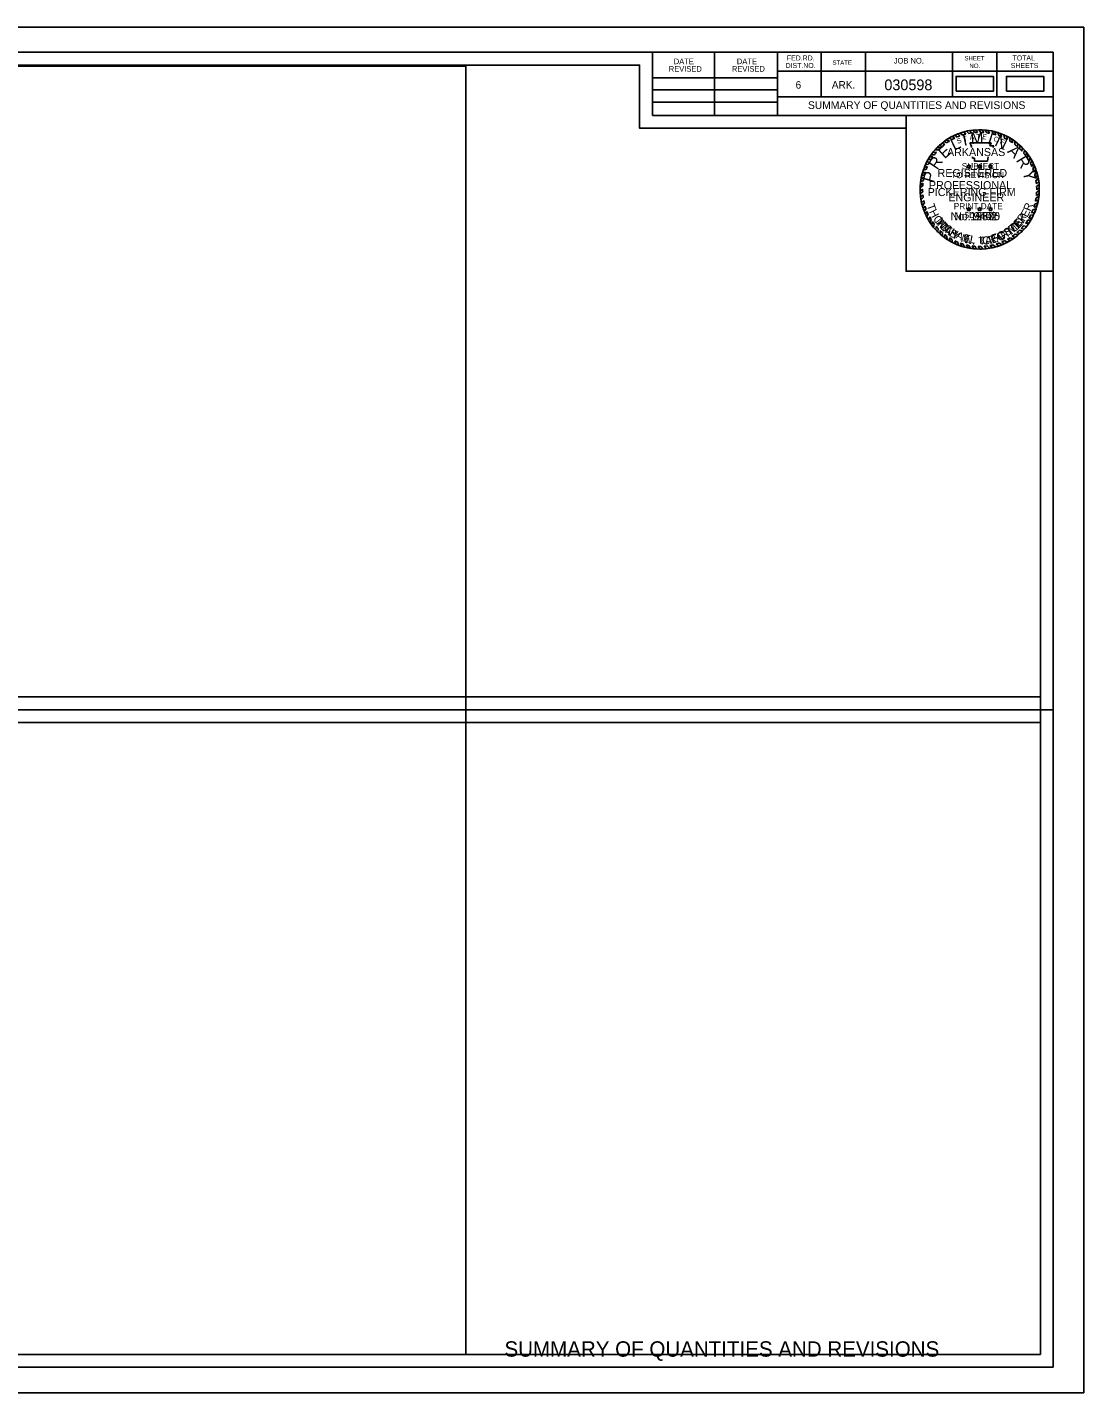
# Model space of a CAD drawing. Extents: x 1369904 to 1372237, y 380119 to 380332.
# Drawn here: x 1372071.9 to 1372236.9, y 380119.1 to 380332.4 of the extents above; entities that cross this region are included whole.
import ezdxf

# ---------------------------------------------------------------- set-up
doc = ezdxf.new("R2010")
doc.units = 0
for name, color, linetype in [('Default', 7, 'Continuous'), ('R_Border', 7, 'Continuous'), ('R_Border Notes', 7, 'Continuous'), ('R_Border Plan-Plan', 7, 'Continuous'), ('R_Border Title', 7, 'Continuous'), ('R_No Plot', 7, 'Continuous'), ('STAMP_PE_CRAFTON', 7, 'Continuous'), ('STAMP_PE_FOSTER', 7, 'Continuous'), ('STAMP_PE_SEAL-INFO', 7, 'Continuous'), ('STAMP_PE_TAEGTMEYER', 7, 'Continuous'), ('STAMP_PE_TXT', 7, 'Continuous'), ('STAMP_PRELIMINARY', 7, 'Continuous')]:
    doc.layers.add(name, color=color, linetype=linetype)

msp = doc.modelspace()

# ---------------------------------------------------------------- linework, layer by layer
at = {"layer": 'Default'}
for points in [[(1371973.99, 380125.04), (1372140.37, 380125.04), (1372140.37, 380326.31), (1371973.99, 380326.31)], [(1372217, 380322.41), (1372222.83, 380322.41), (1372222.83, 380324.72), (1372217, 380324.72)], [(1372224.87, 380322.41), (1372230.7, 380322.41), (1372230.7, 380324.72), (1372224.87, 380324.72)]]:
    msp.add_lwpolyline(points, close=True, dxfattribs=at)
at = {"layer": 'R_Border'}
for p, q in [((1371916, 380328.5), (1372232.18, 380328.5)), ((1372169.54, 380318.62), (1372169.54, 380328.5)), ((1372179.22, 380318.62), (1372179.22, 380328.5)), ((1372189.08, 380328.5), (1372189.08, 380318.62)), ((1372195.92, 380328.5), (1372195.92, 380321.56)), ((1372202.86, 380328.5), (1372202.86, 380321.56)), ((1372216.44, 380328.5), (1372216.44, 380321.56)), ((1372223.38, 380328.5), (1372223.38, 380321.56)), ((1372232.18, 380123.04), (1372232.18, 380328.5)), ((1372232.18, 380325.56), (1372189.08, 380325.56)), ((1372232.18, 380325.58), (1372232.18, 380325.58)), ((1372169.54, 380324.48), (1372189.08, 380324.48)), ((1372169.54, 380322.62), (1372189.08, 380322.62)), ((1372232.18, 380321.56), (1372189.08, 380321.56)), ((1372192.04, 380321.56), (1372232.18, 380321.56)), ((1372169.54, 380320.68), (1372189.08, 380320.68)), ((1372232.18, 380318.62), (1372169.54, 380318.62)), ((1372232.18, 380123.04), (1371916, 380123.04))]:
    msp.add_line(p, q, dxfattribs=at)
at = {"layer": 'R_Border Plan-Plan'}
msp.add_line((1371916, 380225.77), (1372232.18, 380225.77), dxfattribs=at)
at = {"layer": 'R_No Plot'}
for points in [[(1371903.6, 380332.4), (1372236.94, 380332.4), (1372236.94, 380119.06), (1371903.6, 380119.06)], [(1372230.18, 380227.77), (1371918, 380227.77), (1371918, 380326.5), (1372167.54, 380326.5), (1372167.54, 380316.62), (1372185.08, 380316.62), (1372209.18, 380316.62), (1372209.18, 380294.29), (1372230.18, 380294.29)], [(1371918, 380326.5), (1372167.54, 380326.5), (1372167.54, 380316.62), (1372185.08, 380316.62), (1372209.18, 380316.62), (1372209.18, 380294.29), (1372230.18, 380294.29), (1372230.18, 380125.04), (1371918, 380125.04)], [(1372209.18, 380318.62), (1372232.18, 380318.62), (1372232.18, 380294.29), (1372209.18, 380294.29)], [(1371918, 380223.77), (1372230.18, 380223.77), (1372230.18, 380125.04), (1371918, 380125.04)]]:
    msp.add_lwpolyline(points, close=True, dxfattribs=at)
at = {"layer": 'STAMP_PE_SEAL-INFO'}
for p, q in [((1372215.52, 380314.83), (1372215.96, 380314.63)), ((1372215.91, 380315.07), (1372216.34, 380314.85)), ((1372216.36, 380315.33), (1372216.82, 380315.1)), ((1372216.79, 380315.54), (1372217.18, 380315.26)), ((1372217.29, 380315.75), (1372217.59, 380315.43)), ((1372217.64, 380315.88), (1372218.02, 380315.57)), ((1372218.23, 380316.06), (1372218.52, 380315.71)), ((1372218.62, 380316.16), (1372218.98, 380315.82)), ((1372219.1, 380316.26), (1372219.4, 380315.89)), ((1372219.62, 380316.33), (1372219.9, 380315.95)), ((1372220.35, 380315.97), (1372220.04, 380316.37)), ((1372220.85, 380315.98), (1372220.57, 380316.39)), ((1372221.31, 380315.96), (1372221.05, 380316.38)), ((1372221.82, 380315.91), (1372221.52, 380316.35)), ((1372222.24, 380315.84), (1372221.98, 380316.3)), ((1372222.8, 380315.72), (1372222.63, 380316.18)), ((1372223.21, 380315.62), (1372223.05, 380316.09)), ((1372223.66, 380315.47), (1372223.52, 380315.95)), ((1372224.08, 380315.31), (1372223.93, 380315.81)), ((1372224.54, 380315.1), (1372224.43, 380315.6)), ((1372224.98, 380314.87), (1372224.9, 380315.38)), ((1372225.37, 380314.65), (1372225.33, 380315.15)), ((1372225.81, 380314.36), (1372225.77, 380314.88)), ((1372213.38, 380312.86), (1372213.93, 380312.88)), ((1372213.72, 380313.27), (1372214.24, 380313.23)), ((1372214.04, 380313.61), (1372214.59, 380313.57)), ((1372214.38, 380313.94), (1372214.84, 380313.8)), ((1372214.72, 380314.24), (1372215.25, 380314.14)), ((1372215.1, 380314.56), (1372215.56, 380314.36)), ((1372219.16, 380314.36), (1372222.5, 380314.36)), ((1372219.28, 380314.05), (1372219.16, 380314.36)), ((1372219.38, 380313.75), (1372219.28, 380314.05)), ((1372219.39, 380313.64), (1372219.38, 380313.75)), ((1372222.5, 380314.36), (1372222.28, 380313.87)), ((1372222.28, 380313.87), (1372222.91, 380313.87)), ((1372222.91, 380313.87), (1372222.76, 380313.64)), ((1372226.17, 380314.1), (1372226.2, 380314.58)), ((1372226.61, 380313.72), (1372226.63, 380314.25)), ((1372226.92, 380313.43), (1372226.99, 380313.93)), ((1372227.28, 380313.06), (1372227.35, 380313.58)), ((1372227.56, 380312.74), (1372227.69, 380313.21)), ((1372227.88, 380312.32), (1372228.02, 380312.82)), ((1372212.01, 380310.5), (1372212.52, 380310.64)), ((1372212.2, 380310.93), (1372212.7, 380311.03)), ((1372212.39, 380311.32), (1372212.88, 380311.38)), ((1372212.62, 380311.74), (1372213.11, 380311.76)), ((1372212.86, 380312.14), (1372213.38, 380312.18)), ((1372213.1, 380312.49), (1372213.6, 380312.48)), ((1372219.58, 380311.93), (1372219.55, 380312.15)), ((1372219.89, 380311.93), (1372219.58, 380311.93)), ((1372219.89, 380311.5), (1372219.89, 380311.93)), ((1372221.92, 380311.5), (1372219.89, 380311.5)), ((1372221.94, 380311.84), (1372221.92, 380311.5)), ((1372222.02, 380312.15), (1372221.94, 380311.84)), ((1372228.1, 380312.01), (1372228.28, 380312.47)), ((1372228.41, 380311.51), (1372228.59, 380312)), ((1372228.61, 380311.14), (1372228.84, 380311.59)), ((1372228.84, 380310.66), (1372229.07, 380311.15)), ((1372228.98, 380310.32), (1372229.24, 380310.76)), ((1372211.88, 380308.48), (1372211.44, 380308.25)), ((1372211.97, 380308.94), (1372211.5, 380308.69)), ((1372211.6, 380309.18), (1372212.07, 380309.37)), ((1372211.71, 380309.59), (1372212.19, 380309.76)), ((1372211.86, 380310.09), (1372212.35, 380310.23)), ((1372229.18, 380309.77), (1372229.45, 380310.25)), ((1372229.28, 380309.41), (1372229.58, 380309.86)), ((1372229.42, 380308.85), (1372229.73, 380309.3)), ((1372229.49, 380308.47), (1372229.84, 380308.82)), ((1372211.79, 380307.62), (1372211.36, 380307.36)), ((1372211.77, 380307.12), (1372211.36, 380306.79)), ((1372211.78, 380306.72), (1372211.38, 380306.39)), ((1372211.82, 380308.04), (1372211.39, 380307.76)), ((1372229.55, 380307.96), (1372229.92, 380308.3)), ((1372229.55, 380306.11), (1372229.98, 380306.37)), ((1372229.58, 380307.54), (1372229.97, 380307.84)), ((1372229.59, 380306.62), (1372230, 380306.9)), ((1372229.6, 380307.03), (1372230, 380307.35)), ((1372211.81, 380306.22), (1372211.44, 380305.86)), ((1372211.86, 380305.79), (1372211.51, 380305.42)), ((1372211.94, 380305.33), (1372211.6, 380304.96)), ((1372212.03, 380304.91), (1372211.72, 380304.5)), ((1372212.16, 380304.47), (1372211.86, 380304.05)), ((1372229.15, 380304.28), (1372229.64, 380304.48)), ((1372229.3, 380304.77), (1372229.77, 380304.98)), ((1372229.4, 380305.23), (1372229.86, 380305.42)), ((1372229.49, 380305.73), (1372229.94, 380305.95)), ((1372212.3, 380304.04), (1372212.02, 380303.63)), ((1372212.46, 380303.62), (1372212.2, 380303.19)), ((1372212.64, 380303.23), (1372212.41, 380302.77)), ((1372212.87, 380302.77), (1372212.68, 380302.28)), ((1372213.11, 380302.37), (1372212.92, 380301.9)), ((1372213.31, 380302.06), (1372213.2, 380301.51)), ((1372228.2, 380302.27), (1372228.67, 380302.26)), ((1372228.37, 380302.55), (1372228.87, 380302.61)), ((1372228.64, 380303.05), (1372229.13, 380303.12)), ((1372228.8, 380303.39), (1372229.29, 380303.48)), ((1372229.01, 380303.9), (1372229.5, 380304.03)), ((1372213.59, 380301.67), (1372213.49, 380301.14)), ((1372213.89, 380301.29), (1372213.81, 380300.77)), ((1372214.2, 380300.95), (1372214.13, 380300.43)), ((1372214.52, 380300.63), (1372214.49, 380300.1)), ((1372214.86, 380300.32), (1372214.86, 380299.79)), ((1372215.22, 380300.02), (1372215.24, 380299.5)), ((1372226.23, 380300.09), (1372226.7, 380299.95)), ((1372226.5, 380300.32), (1372226.98, 380300.19)), ((1372226.91, 380300.69), (1372227.35, 380300.55)), ((1372227.16, 380300.95), (1372227.64, 380300.86)), ((1372227.55, 380301.38), (1372228.01, 380301.3)), ((1372227.86, 380301.78), (1372228.36, 380301.78)), ((1372215.56, 380299.77), (1372215.6, 380299.25)), ((1372215.99, 380299.49), (1372216.05, 380298.98)), ((1372216.34, 380299.28), (1372216.43, 380298.77)), ((1372216.82, 380299.03), (1372216.98, 380298.51)), ((1372217.19, 380298.87), (1372217.37, 380298.35)), ((1372217.69, 380298.67), (1372217.89, 380298.17)), ((1372218.09, 380298.54), (1372218.32, 380298.05)), ((1372218.6, 380298.4), (1372218.82, 380297.93)), ((1372219, 380298.31), (1372219.25, 380297.86)), ((1372219.5, 380298.23), (1372219.74, 380297.79)), ((1372219.94, 380298.19), (1372220.21, 380297.76)), ((1372220.42, 380298.16), (1372220.72, 380297.74)), ((1372220.88, 380298.16), (1372221.23, 380297.76)), ((1372221.4, 380298.18), (1372221.73, 380297.8)), ((1372221.84, 380298.23), (1372222.21, 380297.87)), ((1372222.28, 380298.3), (1372222.67, 380297.96)), ((1372222.78, 380298.4), (1372223.15, 380298.08)), ((1372223.24, 380298.53), (1372223.65, 380298.23)), ((1372223.73, 380298.69), (1372224.17, 380298.42)), ((1372224.15, 380298.85), (1372224.57, 380298.59)), ((1372224.61, 380299.06), (1372225.09, 380298.85)), ((1372225.01, 380299.28), (1372225.43, 380299.04)), ((1372225.43, 380299.52), (1372225.88, 380299.33)), ((1372225.77, 380299.75), (1372226.21, 380299.56))]:
    msp.add_line(p, q, dxfattribs=at)
for radius, start, end in [(9.32, 123.6199, 126.5906), (9.32, 117.6544, 120.8099), (8.91, 115.6869, 119.1583), (9.32, 111.3124, 114.7026), (8.91, 110.3086, 113.1659), (9.32, 105.2339, 109.0352), (8.91, 104.0352, 107.3615), (9.32, 99.7525, 102.7765), (8.91, 98.258, 101.0329), (9.32, 93.9381, 96.5517), (8.91, 92.1102, 95.0367), (9.32, 87.7298, 90.6707), (8.91, 85.9628, 88.9097), (9.32, 81.9732, 84.8236), (8.91, 79.9264, 82.696), (9.32, 75.3125, 77.9426), (8.91, 73.5575, 76.2314), (9.32, 69.6061, 72.3058), (8.91, 67.6248, 70.504), (9.32, 63.1329, 66.2704), (8.91, 61.1558, 64.3784), (9.32, 56.9003, 60.0942), (9.32, 141.6056, 144.4486), (8.91, 139.301, 142.5873), (9.32, 135.4021, 138.3031), (8.91, 133.1331, 136.2562), (9.32, 129.7326, 132.5376), (8.91, 127.5297, 130.9683), (8.91, 121.9746, 125.11), (8.91, 54.9238, 58.2702), (8.91, 48.3016, 52.0395), (9.32, 50.3492, 53.7159), (8.91, 42.2212, 45.5512), (9.32, 44.3405, 47.3929), (8.91, 36.135, 39.5311), (9.32, 38.1247, 41.2316), (9.32, 152.864, 155.5189), (8.91, 156.3402, 159.2319), (9.32, 147.0072, 149.899), (8.91, 151.0315, 153.573), (8.91, 145.0197, 148.2104), (8.91, 29.9032, 33.6645), (9.32, 31.9614, 35.4294), (8.91, 23.7732, 27.2211), (9.32, 25.9391, 29.0125), (9.32, 19.9538, 23.3141), (9.32, 170.0003, 172.6878), (9.32, 164.3068, 166.894), (9.32, 158.4077, 161.0701), (8.91, 167.9048, 170.9039), (8.91, 162.4331, 165.0013), (8.91, 17.6802, 21.4251), (8.91, 11.5444, 15.2364), (8.91, 5.7599, 9.0606), (9.32, 13.8421, 17.4447), (9.32, 7.5852, 10.8621), (9.32, 175.7409, 178.2066), (9.32, 181.7251, 184.1626), (8.91, 179.6454, 182.2633), (8.91, 173.73, 176.4734), (8.91, 353.8632, 357.1274), (8.91, 359.7329, 3.0639), (9.32, 1.7215, 4.7268), (9.32, 355.7156, 358.9569), (9.32, 187.4204, 190.1927), (9.32, 193.0369, 195.9973), (8.91, 185.4539, 188.234), (8.91, 191.2274, 193.9858), (8.91, 196.9675, 199.8353), (8.91, 341.777, 345.0925), (8.91, 348.0778, 351.3435), (9.32, 343.8925, 347.035), (9.32, 349.8305, 353.0885), (9.32, 198.8967, 201.6281), (9.32, 204.5479, 207.4328), (8.91, 202.7761, 205.4791), (9.32, 210.8636, 213.6571), (8.91, 208.7883, 211.7934), (8.91, 214.1838, 217.2747), (8.91, 323.5851, 327.4407), (9.32, 325.4405, 328.9872), (8.91, 329.5549, 333.2076), (8.91, 335.6038, 339.1858), (9.32, 331.4037, 334.9332), (9.32, 337.3837, 340.9933), (9.32, 216.6115, 219.491), (9.32, 222.48, 225.3801), (8.91, 220.3909, 223.3056), (9.32, 228.3665, 231.348), (8.91, 226.2494, 229.2407), (8.91, 232.229, 234.9336), (8.91, 304.823, 308.5143), (9.32, 306.3721, 310.208), (8.91, 310.7744, 314.3161), (9.32, 312.4518, 315.6633), (8.91, 316.6531, 320.3711), (9.32, 318.2846, 321.8043), (9.32, 234.295, 236.9452), (8.91, 238.2223, 240.8353), (9.32, 240.1977, 242.8613), (8.91, 244.3204, 246.9486), (9.32, 246.576, 249.1558), (8.91, 250.3491, 253.1216), (9.32, 252.5967, 255.3252), (8.91, 256.505, 259.1192), (9.32, 258.4433, 261.1398), (8.91, 262.3783, 265.2012), (9.32, 264.1978, 267.1009), (8.91, 268.3215, 271.277), (9.32, 270.2548, 273.3361), (8.91, 274.6157, 277.4486), (9.32, 276.4239, 279.4357), (8.91, 280.3459, 283.5814), (9.32, 282.3199, 285.3702), (8.91, 286.6423, 289.9783), (9.32, 288.5709, 291.9733), (8.91, 292.8745, 296.1185), (9.32, 294.6481, 298.2166), (8.91, 299.0768, 302.1724), (9.32, 300.621, 303.8703)]:
    msp.add_arc((1372220.68, 380307.07), radius, start, end, dxfattribs=at)
at = {"layer": 'STAMP_PE_TXT'}
for p, q in [((1372218.86, 380310.64), (1372218.66, 380310.78)), ((1372218.66, 380310.78), (1372218.91, 380310.78)), ((1372218.79, 380310.41), (1372218.86, 380310.64)), ((1372218.98, 380310.55), (1372218.79, 380310.41)), ((1372218.91, 380310.78), (1372218.98, 380311.02)), ((1372218.98, 380311.02), (1372219.06, 380310.78)), ((1372219.18, 380310.41), (1372218.98, 380310.55)), ((1372219.06, 380310.78), (1372219.31, 380310.78)), ((1372219.31, 380310.78), (1372219.11, 380310.64)), ((1372219.11, 380310.64), (1372219.18, 380310.41)), ((1372220.56, 380310.64), (1372220.36, 380310.78)), ((1372220.36, 380310.78), (1372220.61, 380310.78)), ((1372220.48, 380310.41), (1372220.56, 380310.64)), ((1372220.68, 380310.55), (1372220.48, 380310.41)), ((1372220.61, 380310.78), (1372220.68, 380311.02)), ((1372220.68, 380311.02), (1372220.76, 380310.78)), ((1372220.88, 380310.41), (1372220.68, 380310.55)), ((1372220.76, 380310.78), (1372221, 380310.78)), ((1372221, 380310.78), (1372220.81, 380310.64)), ((1372220.81, 380310.64), (1372220.88, 380310.41)), ((1372222.26, 380310.64), (1372222.06, 380310.78)), ((1372222.06, 380310.78), (1372222.31, 380310.78)), ((1372222.18, 380310.41), (1372222.26, 380310.64)), ((1372222.38, 380310.55), (1372222.18, 380310.41)), ((1372222.31, 380310.78), (1372222.38, 380311.02)), ((1372222.38, 380311.02), (1372222.46, 380310.78)), ((1372222.58, 380310.41), (1372222.38, 380310.55)), ((1372222.46, 380310.78), (1372222.7, 380310.78)), ((1372222.7, 380310.78), (1372222.5, 380310.64)), ((1372222.5, 380310.64), (1372222.58, 380310.41)), ((1372218.91, 380304.08), (1372218.98, 380304.31)), ((1372218.98, 380304.31), (1372219.06, 380304.08)), ((1372220.61, 380304.08), (1372220.68, 380304.31)), ((1372220.68, 380304.31), (1372220.76, 380304.08)), ((1372222.31, 380304.08), (1372222.38, 380304.31)), ((1372222.38, 380304.31), (1372222.46, 380304.08)), ((1372218.86, 380303.93), (1372218.66, 380304.08)), ((1372218.66, 380304.08), (1372218.91, 380304.08)), ((1372218.79, 380303.7), (1372218.86, 380303.93)), ((1372218.98, 380303.84), (1372218.79, 380303.7)), ((1372219.18, 380303.7), (1372218.98, 380303.84)), ((1372219.06, 380304.08), (1372219.31, 380304.08)), ((1372219.31, 380304.08), (1372219.11, 380303.93)), ((1372219.11, 380303.93), (1372219.18, 380303.7)), ((1372220.56, 380303.93), (1372220.36, 380304.08)), ((1372220.36, 380304.08), (1372220.61, 380304.08)), ((1372220.48, 380303.7), (1372220.56, 380303.93)), ((1372220.68, 380303.84), (1372220.48, 380303.7)), ((1372220.88, 380303.7), (1372220.68, 380303.84)), ((1372220.76, 380304.08), (1372221, 380304.08)), ((1372221, 380304.08), (1372220.81, 380303.93)), ((1372220.81, 380303.93), (1372220.88, 380303.7)), ((1372222.26, 380303.93), (1372222.06, 380304.08)), ((1372222.06, 380304.08), (1372222.31, 380304.08)), ((1372222.18, 380303.7), (1372222.26, 380303.93)), ((1372222.38, 380303.84), (1372222.18, 380303.7)), ((1372222.58, 380303.7), (1372222.38, 380303.84)), ((1372222.46, 380304.08), (1372222.7, 380304.08)), ((1372222.7, 380304.08), (1372222.5, 380303.93)), ((1372222.5, 380303.93), (1372222.58, 380303.7))]:
    msp.add_line(p, q, dxfattribs=at)
at = {"layer": 'STAMP_PRELIMINARY'}
msp.add_circle((1372220.68, 380307.07), 9.32, dxfattribs=at)

# ---------------------------------------------------------------- texts
at = {"layer": 'R_Border'}
for s, height, p in [('FED.RD.', 0.782, (1372190.56, 380327.22)), ('JOB NO.', 0.879, (1372207.26, 380326.74)), ('SHEET', 0.684, (1372218.3, 380327.22)), ('TOTAL', 0.782, (1372225.82, 380327.22)), ('REVISED', 0.879, (1372172.1, 380325.46)), ('DATE', 0.879, (1372172.88, 380326.64)), ('REVISED', 0.879, (1372181.96, 380325.46)), ('DATE', 0.879, (1372182.74, 380326.64)), ('DIST.NO.', 0.782, (1372190.36, 380326.04)), ('STATE', 0.684, (1372197.68, 380326.54)), ('NO.', 0.684, (1372219.08, 380326.04)), ('SHEETS', 0.782, (1372225.54, 380326.04)), ('6', 1.17, (1372191.92, 380322.82)), ('ARK.', 1.172, (1372197.58, 380322.82))]:
    msp.add_text(s, height=height, dxfattribs=at).set_placement(p)
at = {"layer": 'R_Border Notes'}
for s, height, p in [('030598', 1.68, (1372205.79, 380322.57)), ('SUMMARY OF QUANTITIES AND REVISIONS', 1.2, (1372193.85, 380319.64))]:
    msp.add_text(s, height=height, dxfattribs=at).set_placement(p)
at = {"layer": 'R_Border Title'}
msp.add_text('SUMMARY OF QUANTITIES AND REVISIONS', height=2.4, dxfattribs=at).set_placement((1372146.42, 380124.69))
at = {"layer": 'STAMP_PE_CRAFTON'}
for s, rotation, p in [('T', 310.7442, (1372213.65, 380301.97)), ('N', 49.2411, (1372226.97, 380301.09)), ('O', 317.6422, (1372214.32, 380301.15)), ('N', 324.4537, (1372215.16, 380300.37)), ('Y', 331.1686, (1372216.19, 380299.65)), ('N', 347.4752, (1372218.25, 380298.74)), ('R', 14.8189, (1372222.25, 380298.52)), ('A', 20.5125, (1372223.36, 380298.82)), ('F', 28.7821, (1372224.34, 380299.2)), ('T', 34.1136, (1372225.26, 380299.71)), ('O', 41.8391, (1372226.12, 380300.31)), ('.', 356.8926, (1372219.48, 380298.46)), ('C', 6.0117, (1372221.15, 380298.41))]:
    msp.add_text(s, height=1.25, rotation=rotation, dxfattribs=at).set_placement(p)
msp.add_text('No. 12370', height=1.25, dxfattribs=at).set_placement((1372216.14, 380302.26))
at = {"layer": 'STAMP_PE_FOSTER'}
for s, rotation, p in [('M', 308.339, (1372213.8, 380302.09)), ('E', 46.9613, (1372226.68, 380301.06)), ('R', 54.5031, (1372227.41, 380301.88)), ('I', 314.1842, (1372214.6, 380301.15)), ('C', 319.8733, (1372214.95, 380300.8)), ('H', 327.7235, (1372215.88, 380300.06)), ('A', 335.7276, (1372216.86, 380299.48)), ('E', 343.5779, (1372218, 380299.01)), ('L', 350.8115, (1372219.06, 380298.73)), ('F', 15.8691, (1372222.72, 380298.82)), ('O', 23.719, (1372223.76, 380299.15)), ('S', 31.7234, (1372224.87, 380299.68)), ('T', 39.4194, (1372225.83, 380300.31)), ('L', 1.2666, (1372220.6, 380298.58)), ('.', 6.8035, (1372221.64, 380298.63))]:
    msp.add_text(s, height=1.2, rotation=rotation, dxfattribs=at).set_placement(p)
msp.add_text('No. 9402', height=1.25, dxfattribs=at).set_placement((1372216.67, 380302.26))
at = {"layer": 'STAMP_PE_TAEGTMEYER'}
for s, rotation, p in [('T', 289.646, (1372212.38, 380304.58)), ('R', 69.57, (1372228.63, 380303.58)), ('H', 296.7339, (1372212.74, 380303.59)), ('O', 303.7708, (1372213.33, 380302.49)), ('M', 314.2033, (1372213.98, 380301.53)), ('E', 46.8094, (1372226.72, 380300.84)), ('Y', 53.9986, (1372227.46, 380301.66)), ('E', 63.0984, (1372228.13, 380302.6)), ('A', 321.0594, (1372214.95, 380300.57)), ('S', 327.8239, (1372215.77, 380299.93)), ('N', 344.2727, (1372217.67, 380298.92)), ('E', 17.6836, (1372222.63, 380298.6)), ('G', 23.3052, (1372223.68, 380298.93)), ('T', 31.466, (1372224.78, 380299.42)), ('M', 39.3, (1372225.68, 380299.97)), ('.', 350.6464, (1372218.88, 380298.59)), ('T', 3.0061, (1372220.55, 380298.39)), ('A', 8.9826, (1372221.59, 380298.44))]:
    msp.add_text(s, height=1.25, rotation=rotation, dxfattribs=at).set_placement(p)
msp.add_text('No. 19605', height=1.25, dxfattribs=at).set_placement((1372216.14, 380302.26))
at = {"layer": 'STAMP_PE_TXT'}
for s, rotation, p in [('S', 23.5541, (1372217.28, 380314.17)), ('T', 16.311, (1372218.2, 380314.54)), ('A', 9.0679, (1372219.17, 380314.8)), ('T', 1.8248, (1372220.15, 380314.93)), ('E', 355.2002, (1372221.06, 380314.93)), ('O', 342.2506, (1372222.79, 380314.66)), ('F', 335.0075, (1372223.76, 380314.32))]:
    msp.add_text(s, height=0.781, rotation=rotation, dxfattribs=at).set_placement(p)
for s, p in [('ARKANSAS', (1372215.58, 380312.28)), ('REGISTERED', (1372214.1, 380309.01)), ('PROFESSIONAL', (1372212.75, 380307.11)), ('ENGINEER', (1372215.79, 380305.21))]:
    msp.add_text(s, height=1.25, dxfattribs=at).set_placement(p)
at = {"layer": 'STAMP_PRELIMINARY'}
for s, rotation, p in [('L', 25.513, (1372216.69, 380313.09)), ('I', 12.5248, (1372218.22, 380313.85)), ('M', 3.1074, (1372219.32, 380314.16)), ('I', 342.3164, (1372221.79, 380314.23)), ('N', 333.9382, (1372222.89, 380313.96)), ('E', 42.3578, (1372215.21, 380311.76)), ('A', 315.6579, (1372224.93, 380312.93)), ('R', 56.2292, (1372214.05, 380310.03)), ('R', 301.3831, (1372226.3, 380311.62)), ('P', 73.913, (1372213.5, 380308.01)), ('Y', 283.2593, (1372227.38, 380309.83))]:
    msp.add_text(s, height=1.8, rotation=rotation, dxfattribs=at).set_placement(p)
for s, height, p in [('SUBJECT', 0.96, (1372217.88, 380310.22)), ('TO REVISION', 0.96, (1372216.22, 380308.83)), ('PICKERING FIRM', 1.25, (1372212.56, 380306.03)), ('PRINT DATE', 0.96, (1372216.64, 380303.98)), ('$DATE$', 0.96, (1372218.32, 380302.6))]:
    msp.add_text(s, height=height, dxfattribs=at).set_placement(p)

doc.saveas('drawing.dxf')
